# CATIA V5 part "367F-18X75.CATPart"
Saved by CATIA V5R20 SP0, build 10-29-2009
Part number: 367F-18X75
Definition: NONE
Nomenclature: 367F-18X75
Source: Unknown
Description: 367F-18X75
Bounding box of the stored display mesh (mm): x 0 to 75, y -14 to 14, z -14 to 14
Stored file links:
  C:\Users\Utente\Desktop\IO LAVORO\3D X SITO CF\X SITO\PLASTICA\3D files 367\367F-18X75.CATPart
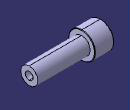
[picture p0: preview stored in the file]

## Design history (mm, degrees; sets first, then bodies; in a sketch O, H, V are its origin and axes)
Body1 "367F-18X75" (main body)
  Solid1: solid without history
